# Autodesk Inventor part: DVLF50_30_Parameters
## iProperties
Created: 2010-03
Part Number: DVLF50_30_Parameters
Document SubType Name: Modeling
Designer: TB
Density: 1 g/cm^3
Slaglengde: 100.000 mm
Vinkel_Plussport: 0.00 deg
Vinkel_Minusport: 0.00 deg
Forlengelse_rør: 0.000 mm
Author: TB
